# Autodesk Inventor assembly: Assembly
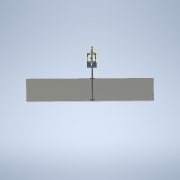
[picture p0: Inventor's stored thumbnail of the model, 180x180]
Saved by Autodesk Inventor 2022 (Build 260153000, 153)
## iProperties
Created: 2021-07
Part Number: Assembly
Document SubType Name: Assembly
Designer: 91876
Mass: 46655.7 g
Surface Area: 45969.5 cm^2
Volume: 46667.2 cm^3
Density: 0.999754 g/cm^3
Author: 91876
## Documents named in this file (17)
- C:\Users\91876\Documents\Inventor files\rope walking bot\Assembly.iam
- C:\Users\91876\Documents\Inventor files\rope walking bot\pannel.ipt
- C:\Users\91876\Documents\Inventor files\rope walking bot\motor.ipt
- C:\Users\91876\Documents\Inventor files\rope walking bot\motor pin.ipt
- C:\Users\91876\Documents\Inventor files\rope walking bot\bigwheel.ipt
- C:\Users\91876\Documents\Inventor files\rope walking bot\smallwheel.ipt
- C:\Users\91876\Documents\Inventor files\rope walking bot\load and pannel.ipt
- C:\Users\91876\Documents\Inventor files\rope walking bot\axle through wheel.ipt
- C:\Users\91876\Documents\Inventor files\rope walking bot\motor wheel.ipt
- C:\Users\91876\Documents\Inventor files\rope walking bot\Assembly\Design Accelerator\V-Belt transmission4.iam
- C:\Users\91876\Documents\Inventor files\rope walking bot\motor bolt.ipt
- C:\Users\91876\Documents\Inventor files\rope walking bot\Load carrier 2nd.ipt
- C:\Users\91876\Documents\Inventor files\rope walking bot\load_door 2nd.ipt
- C:\Users\91876\Documents\Inventor files\rope walking bot\rope.ipt
- C:\Users\91876\Documents\Inventor files\rope walking bot\rope Support.ipt
- C:\Users\91876\Documents\Inventor files\rope walking bot\rope Support pin.ipt
- C:\Users\91876\Documents\Inventor files\rope walking bot\base.ipt
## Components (24 placed, 16 different names)
1. pannel:1 — Mate:1, Flush:1, Flush:2, Mate:42, Flush:4, Mate:43, Mate:44, Mate:45, Flush:5, Mate:46, Flush:6
2. motor:1 — Mate:1, Flush:1, Flush:2, Mate:2, Flush:3, Mate:84, Mate:85
3. motor pin:1 — Mate:2, Flush:3, Mate:79, Flush:15, Mate:98
4. load and pannel:1 — Mate:45, Flush:5, Mate:68, Flush:12, Mate:95
5. load and pannel:2 — Mate:43, Mate:44, Mate:71, Flush:11, Mate:91, Mate:96
6. load and pannel:3 — Mate:46, Flush:6, Mate:69, Flush:13, Mate:92, Mate:94
7. load and pannel:4 — Mate:42, Flush:4, Mate:70, Flush:14
8. smallwheel:1 — Mate:62, Mate:76, Mate:77, Mate:89
9. smallwheel:2 — Mate:65, Mate:72, Mate:75
10. bigwheel:1 — Mate:62, Mate:76, Mate:78, Tangent:3, Tangent:4
11. bigwheel:2 — Mate:65, Mate:73, Mate:74, Tangent:1, Tangent:2
12. axle through wheel:1 — Mate:68, Mate:69, Flush:12, Flush:13, Mate:72, Mate:73, Mate:74, Mate:75
13. axle through wheel:2 — Mate:70, Mate:71, Flush:11, Flush:14, Mate:77, Mate:78
14. motor wheel:1 — Mate:79, Flush:15, Mate:88, Mate:90, Mate:98
15. V-Belt transmission:1 [sub-assembly] — Mate:88, Mate:89, Mate:90
16. motor bolt:1 — Mate:84, Mate:85
17. Load carrier 2nd:1 — Mate:91, Mate:92, Mate:94, Mate:95, Mate:96, Mate:97, Flush:16
18. load_door 2nd:1 — Mate:97, Flush:16
19. rope:1 — Tangent:1, Tangent:2, Tangent:3, Tangent:4, Mate:99, Mate:100, Mate:101, Mate:102, Mate:104, Mate:106
20. rope Support:1 — Mate:99, Mate:100, Mate:103, Mate:107, Flush:18
21. rope Support:2 — Mate:101, Mate:102, Mate:105, Mate:108, Flush:17
22. rope Support pin:1 — Mate:103, Mate:104
23. rope Support pin:2 — Mate:105, Mate:106
24. base:1 — Mate:107, Mate:108, Flush:17, Flush:18
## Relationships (61: Mate 43, Flush 14, Tangent 4)
- Mate:1: pannel:1 ↔ motor:1
- Flush:1: pannel:1 ↔ motor:1
- Flush:2: pannel:1 ↔ motor:1
- Mate:2: motor:1 ↔ motor pin:1
- Flush:3: motor:1 ↔ motor pin:1
- Mate:42: pannel:1 ↔ load and pannel:4
- Flush:4: pannel:1 ↔ load and pannel:4
- Mate:43: pannel:1 ↔ load and pannel:2
- Mate:44: pannel:1 ↔ load and pannel:2
- Mate:45: pannel:1 ↔ load and pannel:1
- Flush:5: pannel:1 ↔ load and pannel:1
- Mate:46: pannel:1 ↔ load and pannel:3
- Flush:6: pannel:1 ↔ load and pannel:3
- Mate:62: smallwheel:1 ↔ bigwheel:1
- Mate:65: smallwheel:2 ↔ bigwheel:2
- Mate:68: load and pannel:1 ↔ axle through wheel:1
- Mate:69: load and pannel:3 ↔ axle through wheel:1
- Mate:70: load and pannel:4 ↔ axle through wheel:2
- Mate:71: load and pannel:2 ↔ axle through wheel:2
- Flush:11: load and pannel:2 ↔ axle through wheel:2
- Flush:12: load and pannel:1 ↔ axle through wheel:1
- Flush:13: load and pannel:3 ↔ axle through wheel:1
- Flush:14: load and pannel:4 ↔ axle through wheel:2
- Mate:72: smallwheel:2 ↔ axle through wheel:1
- Mate:73: bigwheel:2 ↔ axle through wheel:1
- Mate:74: bigwheel:2 ↔ axle through wheel:1
- Mate:75: smallwheel:2 ↔ axle through wheel:1
- Mate:76: smallwheel:1 ↔ bigwheel:1
- Mate:77: smallwheel:1 ↔ axle through wheel:2
- Mate:78: bigwheel:1 ↔ axle through wheel:2
- Mate:79: motor pin:1 ↔ motor wheel:1
- Flush:15: motor pin:1 ↔ motor wheel:1
- Mate:84: motor:1 ↔ motor bolt:1
- Mate:85: motor:1 ↔ motor bolt:1
- Mate:88: motor wheel:1 ↔ V-Belt transmission:1
- Mate:89: smallwheel:1 ↔ V-Belt transmission:1
- Mate:90: motor wheel:1 ↔ V-Belt transmission:1
- Mate:91: load and pannel:2 ↔ Load carrier 2nd:1
- Mate:92: load and pannel:3 ↔ Load carrier 2nd:1
- Mate:94: load and pannel:3 ↔ Load carrier 2nd:1
- Mate:95: load and pannel:1 ↔ Load carrier 2nd:1
- Mate:96: load and pannel:2 ↔ Load carrier 2nd:1
- Mate:97: Load carrier 2nd:1 ↔ load_door 2nd:1
- Flush:16: Load carrier 2nd:1 ↔ load_door 2nd:1
- Mate:98: motor pin:1 ↔ motor wheel:1
- Tangent:1: bigwheel:2 ↔ rope:1
- Tangent:2: bigwheel:2 ↔ rope:1
- Tangent:3: bigwheel:1 ↔ rope:1
- Tangent:4: bigwheel:1 ↔ rope:1
- Mate:99: rope:1 ↔ rope Support:1
- Mate:100: rope:1 ↔ rope Support:1
- Mate:101: rope:1 ↔ rope Support:2
- Mate:102: rope:1 ↔ rope Support:2
- Mate:103: rope Support:1 ↔ rope Support pin:1
- Mate:104: rope:1 ↔ rope Support pin:1
- Mate:105: rope Support:2 ↔ rope Support pin:2
- Mate:106: rope:1 ↔ rope Support pin:2
- Mate:107: rope Support:1 ↔ base:1
- Mate:108: rope Support:2 ↔ base:1
- Flush:17: rope Support:2 ↔ base:1
- Flush:18: rope Support:1 ↔ base:1
